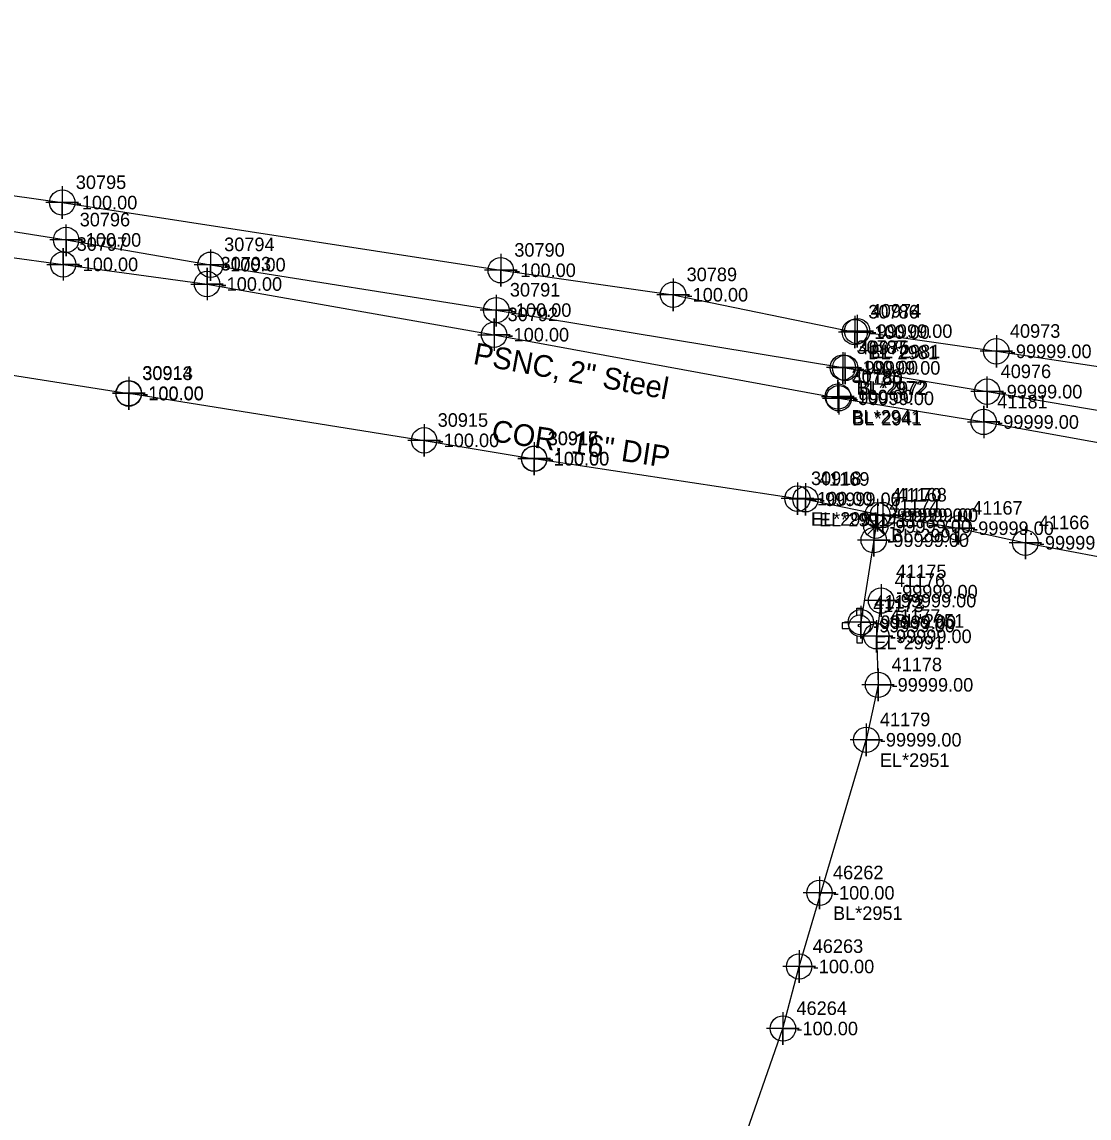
# Model space of a CAD drawing. Extents: x 2083698 to 2094313, y 743246 to 752873.
# Drawn here: x 2090310.6 to 2090507.3, y 744196.6 to 744398.7 of the extents above; entities that cross this region are included whole.
import ezdxf

# ---------------------------------------------------------------- set-up
doc = ezdxf.new("R2010")
doc.units = 0
for name, color, linetype in [('COGO Default Chain', 7, 'Continuous'), ('COGO Default Curve', 7, 'Continuous'), ('COGO Default Point Number', 7, 'Continuous'), ('Default Symbol CELL', 7, 'Continuous'), ('Default Symbol Cogo Number', 7, 'Continuous'), ('Exist Property Corner CELL', 7, 'Continuous'), ('Exist Property Iron Pin Leader', 7, 'Continuous'), ('Exist Property Iron Pin Text', 7, 'Continuous'), ('Exist Property Line', 7, 'Continuous'), ('Exist Property Line Leader', 7, 'Continuous'), ('Exist Property Monument Leader', 7, 'Continuous'), ('Exist Property Monument Text', 7, 'Continuous'), ('Exist Right of Way Easement Line', 7, 'Continuous'), ('Exist Right of Way Easement Line Leader', 7, 'Continuous'), ('Exist Right of Way Easement Line Text', 7, 'Continuous'), ('Exist Right of Way Line', 7, 'Continuous'), ('Exist Right of Way Line Leader', 7, 'Continuous'), ('Exist Right of Way Line Text', 7, 'Continuous'), ('Exist Right of Way Width CELL', 7, 'Continuous'), ('Exist Roads EOP', 7, 'Continuous'), ('Exist Roads EOP Leader', 7, 'Continuous'), ('Exist Roads EOP Text', 7, 'Continuous'), ('Exist Utilities Gas UG Line SUE LOS B', 7, 'Continuous'), ('Exist Utilities Gas UG Line SUE LOS B Text', 7, 'Continuous'), ('Exist Utilities Power Joint Use Telephone Cogo Elevation', 7, 'Continuous'), ('Exist Utilities Power Joint Use Telephone Cogo Number', 7, 'Continuous'), ('Exist Utilities Power UG Cable SUE LOS B', 7, 'Continuous'), ('Exist Utilities Telephone UG Conduit SUE LOS B', 7, 'Continuous'), ('Exist Utilities TV UG Cable SUE LOS B', 7, 'Continuous'), ('Exist Utilities Water UG Line SUE LOS B', 7, 'Continuous'), ('Exist Utilities Water UG Line SUE LOS B Text', 7, 'Continuous'), ('Old_Level_20', 7, 'Continuous'), ('Raster_Level_1', 7, 'Continuous'), ('Scratch_Level_2', 7, 'Continuous'), ('Scratch_Level_3', 7, 'Continuous')]:
    doc.layers.add(name, color=color, linetype=linetype)

msp = doc.modelspace()

# ---------------------------------------------------------------- linework, layer by layer
at = {"layer": 'COGO Default Curve'}
for points in [[(2090315.18, 744354.01), (2090321.18, 744354.01), (2090318.18, 744354.01), (2090318.18, 744357.01), (2090318.18, 744351.01)], [(2090341.72, 744350.39), (2090347.72, 744350.39), (2090344.72, 744350.39), (2090344.72, 744353.39), (2090344.72, 744347.39)], [(2090394.63, 744341.04), (2090400.63, 744341.04), (2090397.63, 744341.04), (2090397.63, 744344.04), (2090397.63, 744338.04)], [(2090458.03, 744329.64), (2090464.03, 744329.64), (2090461.03, 744329.64), (2090461.03, 744332.64), (2090461.03, 744326.64)], [(2090458.19, 744329.32), (2090464.19, 744329.32), (2090461.19, 744329.32), (2090461.19, 744332.32), (2090461.19, 744326.32)], [(2090484.91, 744324.95), (2090490.91, 744324.95), (2090487.91, 744324.95), (2090487.91, 744327.95), (2090487.91, 744321.95)]]:
    msp.add_lwpolyline(points, dxfattribs=at)
for centre in [(2090318.18, 744354.01), (2090344.72, 744350.39), (2090397.63, 744341.04), (2090461.03, 744329.64), (2090461.19, 744329.32), (2090487.91, 744324.95)]:
    msp.add_circle(centre, 2.34, dxfattribs=at)
at = {"layer": 'COGO Default Point Number'}
for points in [[(2090330.28, 744333.26), (2090330.28, 744327.26), (2090330.28, 744330.26), (2090333.28, 744330.26), (2090327.28, 744330.26)], [(2090330.28, 744333.18), (2090330.28, 744327.18), (2090330.28, 744330.18), (2090333.28, 744330.18), (2090327.28, 744330.18)], [(2090384.74, 744324.56), (2090384.74, 744318.56), (2090384.74, 744321.56), (2090387.74, 744321.56), (2090381.74, 744321.56)], [(2090405.02, 744321.15), (2090405.02, 744315.15), (2090405.02, 744318.15), (2090408.02, 744318.15), (2090402.02, 744318.15)], [(2090405.04, 744321.2), (2090405.04, 744315.2), (2090405.04, 744318.2), (2090408.04, 744318.2), (2090402.04, 744318.2)], [(2090453.57, 744313.81), (2090453.57, 744307.81), (2090453.57, 744310.81), (2090456.57, 744310.81), (2090450.57, 744310.81)], [(2090455.05, 744313.69), (2090455.05, 744307.69), (2090455.05, 744310.69), (2090458.05, 744310.69), (2090452.05, 744310.69)], [(2090468.33, 744310.75), (2090468.33, 744304.75), (2090468.33, 744307.75), (2090471.33, 744307.75), (2090465.33, 744307.75)], [(2090469.31, 744310.78), (2090469.31, 744304.78), (2090469.31, 744307.78), (2090472.31, 744307.78), (2090466.31, 744307.78)], [(2090483.29, 744308.36), (2090483.29, 744302.36), (2090483.29, 744305.36), (2090486.29, 744305.36), (2090480.29, 744305.36)], [(2090467.64, 744306.15), (2090467.64, 744300.15), (2090467.64, 744303.15), (2090470.64, 744303.15), (2090464.64, 744303.15)], [(2090495.59, 744305.68), (2090495.59, 744299.68), (2090495.59, 744302.68), (2090498.59, 744302.68), (2090492.59, 744302.68)], [(2090465.25, 744291.03), (2090465.25, 744285.03), (2090465.25, 744288.03), (2090468.25, 744288.03), (2090462.25, 744288.03)]]:
    msp.add_lwpolyline(points, dxfattribs=at)
for centre in [(2090330.28, 744330.26), (2090330.28, 744330.18), (2090384.74, 744321.56), (2090405.02, 744318.15), (2090405.04, 744318.2), (2090453.57, 744310.81), (2090455.05, 744310.69), (2090468.33, 744307.75), (2090469.31, 744307.78), (2090483.29, 744305.36), (2090467.64, 744303.15), (2090495.59, 744302.68), (2090465.25, 744288.03)]:
    msp.add_circle(centre, 2.34, dxfattribs=at)
at = {"layer": 'Exist Property Iron Pin Text'}
for points in [[(2090468.99, 744295.01), (2090468.99, 744289.01), (2090468.99, 744292.01), (2090471.99, 744292.01), (2090465.99, 744292.01)], [(2090468.13, 744288.43), (2090468.13, 744282.43), (2090468.13, 744285.43), (2090471.13, 744285.43), (2090465.13, 744285.43)], [(2090468.43, 744279.48), (2090468.43, 744273.48), (2090468.43, 744276.48), (2090471.43, 744276.48), (2090465.43, 744276.48)], [(2090466.27, 744269.34), (2090466.27, 744263.34), (2090466.27, 744266.34), (2090469.27, 744266.34), (2090463.27, 744266.34)], [(2090457.63, 744241.12), (2090457.63, 744235.12), (2090457.63, 744238.12), (2090460.63, 744238.12), (2090454.63, 744238.12)], [(2090453.89, 744227.54), (2090453.89, 744221.54), (2090453.89, 744224.54), (2090456.89, 744224.54), (2090450.89, 744224.54)], [(2090450.89, 744216.1), (2090450.89, 744210.1), (2090450.89, 744213.1), (2090453.89, 744213.1), (2090447.89, 744213.1)]]:
    msp.add_lwpolyline(points, dxfattribs=at)
for centre in [(2090468.99, 744292.01), (2090468.13, 744285.43), (2090468.43, 744276.48), (2090466.27, 744266.34), (2090457.63, 744238.12), (2090453.89, 744224.54), (2090450.89, 744213.1)]:
    msp.add_circle(centre, 2.34, dxfattribs=at)
at = {"layer": 'Exist Property Line Leader'}
for points in [[(2090318.02, 744368.41), (2090318.02, 744362.41), (2090318.02, 744365.41), (2090321.02, 744365.41), (2090315.02, 744365.41)], [(2090398.87, 744355.93), (2090398.87, 744349.93), (2090398.87, 744352.93), (2090401.87, 744352.93), (2090395.87, 744352.93)], [(2090430.64, 744351.41), (2090430.64, 744345.41), (2090430.64, 744348.41), (2090433.64, 744348.41), (2090427.64, 744348.41)], [(2090464.14, 744344.53), (2090464.14, 744338.53), (2090464.14, 744341.53), (2090467.14, 744341.53), (2090461.14, 744341.53)], [(2090464.58, 744344.7), (2090464.58, 744338.7), (2090464.58, 744341.7), (2090467.58, 744341.7), (2090461.58, 744341.7)], [(2090490.24, 744340.98), (2090490.24, 744334.98), (2090490.24, 744337.98), (2090493.24, 744337.98), (2090487.24, 744337.98)]]:
    msp.add_lwpolyline(points, dxfattribs=at)
for centre in [(2090318.02, 744365.41), (2090398.87, 744352.93), (2090430.64, 744348.41), (2090464.14, 744341.53), (2090464.58, 744341.7), (2090490.24, 744337.98)]:
    msp.add_circle(centre, 2.34, dxfattribs=at)
at = {"layer": 'Exist Right of Way Line Text'}
for points in [[(2090318.71, 744361.34), (2090318.74, 744355.52), (2090318.73, 744358.52), (2090321.74, 744358.52), (2090315.74, 744358.52)], [(2090345.34, 744356.77), (2090345.37, 744350.95), (2090345.35, 744353.95), (2090348.37, 744353.95), (2090342.37, 744353.95)], [(2090398.02, 744348.39), (2090398.05, 744342.58), (2090398.04, 744345.58), (2090401.05, 744345.58), (2090395.05, 744345.58)], [(2090461.92, 744337.81), (2090461.95, 744332), (2090461.94, 744335), (2090464.95, 744335), (2090458.95, 744335)], [(2090462.33, 744337.74), (2090462.36, 744331.92), (2090462.34, 744334.92), (2090465.36, 744334.92), (2090459.36, 744334.92)], [(2090488.51, 744333.35), (2090488.54, 744327.54), (2090488.53, 744330.54), (2090491.54, 744330.54), (2090485.54, 744330.54)]]:
    msp.add_lwpolyline(points, dxfattribs=at)
for centre in [(2090318.74, 744358.52), (2090345.37, 744353.95), (2090398.05, 744345.58), (2090461.95, 744335), (2090462.36, 744334.92), (2090488.54, 744330.54)]:
    msp.add_circle(centre, 2.34, dxfattribs=at)
at = {"layer": 'Exist Roads EOP'}
msp.add_lwpolyline([(2090469.6, 744307.29), (2090466.45, 744304.14), (2090468.02, 744305.72), (2090469.6, 744304.14), (2090466.45, 744307.29)], dxfattribs=at)
msp.add_circle((2090468.02, 744305.72), 2.23, dxfattribs=at)
at = {"layer": 'Exist Utilities Gas UG Line SUE LOS B'}
for points in [[(2089711.55, 744387.62), (2089756.53, 744385.83), (2089770.13, 744385.56), (2089791.66, 744384.63), (2089831.15, 744384.29), (2089852.65, 744384.93), (2089877.76, 744384.56), (2089910.17, 744383.48), (2089956.91, 744382.91), (2090010.13, 744381.65), (2090060.73, 744379.21), (2090117.92, 744377.86), (2090174.06, 744371.58), (2090201.47, 744368.61), (2090259.26, 744361.47), (2090264.98, 744360.29), (2090285.89, 744358.43), (2090318.18, 744354.01), (2090344.72, 744350.39), (2090397.63, 744341.04), (2090461.19, 744329.32)], [(2090461.19, 744329.32), (2090487.91, 744324.95), (2090517.18, 744319.69), (2090542.84, 744315.5), (2090566.72, 744310.47), (2090590.57, 744306.9), (2090618.26, 744302.32), (2090647, 744297.28), (2090679.19, 744292), (2090706.38, 744286.46), (2090732.53, 744282.44), (2090769.33, 744275.59), (2090790.43, 744272.14), (2090815.88, 744267.62), (2090833.41, 744265.34), (2090852.1, 744262.08), (2090862.55, 744260.39), (2090870.48, 744259.26), (2090891.68, 744256.92)]]:
    msp.add_lwpolyline(points, dxfattribs=at)
at = {"layer": 'Exist Utilities Power UG Cable SUE LOS B'}
for points in [[(2090468.99, 744292.01), (2090468.13, 744285.43), (2090468.43, 744276.48), (2090466.27, 744266.34)], [(2090377.35, 743925.53), (2090384.33, 743956.33), (2090390.69, 743987.52), (2090394.74, 743998.37), (2090397.24, 744005.48), (2090401.27, 744023.39), (2090406.08, 744051.45), (2090412.73, 744076.91), (2090420.03, 744103.97), (2090427.25, 744131.27), (2090433.9, 744157.45), (2090437.58, 744171.49), (2090442.95, 744190.35), (2090450.89, 744213.1), (2090453.89, 744224.54), (2090466.27, 744266.34)]]:
    msp.add_lwpolyline(points, dxfattribs=at)
at = {"layer": 'Exist Utilities Telephone UG Conduit SUE LOS B'}
for points in [[(2089543.2, 744398.02), (2089618.15, 744395.85), (2089665.91, 744394.38), (2089690.71, 744394.08), (2089710.79, 744393.02), (2089756.88, 744391.89), (2089831.79, 744390.27), (2089878.22, 744389.02), (2089910.45, 744388.28), (2089956.7, 744387.8), (2090010.24, 744385.92), (2090061.06, 744385.11), (2090118.44, 744382.35), (2090174.93, 744380.66), (2090202.11, 744377.17), (2090261.38, 744368.82), (2090283.03, 744364.22), (2090318.74, 744358.52), (2090345.37, 744353.95), (2090398.05, 744345.58), (2090461.95, 744335)], [(2090462.36, 744334.92), (2090488.54, 744330.54), (2090518.65, 744325.49)]]:
    msp.add_lwpolyline(points, dxfattribs=at)
at = {"layer": 'Exist Utilities TV UG Cable SUE LOS B'}
for points in [[(2089818.55, 744396.88), (2089855.21, 744398.72), (2089896.27, 744398.25), (2089929.74, 744398.05), (2089956.2, 744393.63), (2090010.98, 744390.83), (2090060.95, 744389.12), (2090118.27, 744387.79), (2090170.32, 744384.2), (2090201.62, 744382.33), (2090259.14, 744373.69), (2090318.02, 744365.41), (2090398.87, 744352.93), (2090430.64, 744348.41), (2090464.14, 744341.53)], [(2090464.58, 744341.7), (2090490.24, 744337.98), (2090519.65, 744333.6), (2090542.68, 744330.23), (2090567.11, 744325.5), (2090592.51, 744321.91), (2090619.05, 744316.63), (2090647.22, 744313.33), (2090660.52, 744312.34), (2090662.78, 744311.44), (2090662.54, 744309.61), (2090660.59, 744295.7), (2090657.83, 744275.6), (2090655.3, 744265.25), (2090654.22, 744261.01)]]:
    msp.add_lwpolyline(points, dxfattribs=at)
at = {"layer": 'Exist Utilities Water UG Line SUE LOS B'}
for points in [[(2090031.62, 744360.45), (2090061.58, 744359.55), (2090104.79, 744357.37), (2090104.78, 744357.38), (2090126.49, 744355.64), (2090157.05, 744353.17), (2090186.38, 744350.39), (2090228.99, 744344.98), (2090258.61, 744341.12), (2090292.45, 744336.17), (2090330.28, 744330.18), (2090330.28, 744330.26), (2090384.74, 744321.56), (2090405.02, 744318.15), (2090405.04, 744318.2), (2090453.57, 744310.81)], [(2090455.05, 744310.69), (2090469.31, 744307.78), (2090483.29, 744305.36), (2090495.59, 744302.68), (2090517.19, 744298.58), (2090540.95, 744294.42), (2090568, 744290.02), (2090579.85, 744288), (2090599.72, 744285.07), (2090608.58, 744283.42), (2090615.61, 744281.71)], [(2090468.33, 744307.75), (2090467.64, 744303.15), (2090465.25, 744288.03)]]:
    msp.add_lwpolyline(points, dxfattribs=at)
at = {"layer": 'Raster_Level_1'}
msp.add_line((2090465.03, 744287.4), (2090465.03, 744287.4), dxfattribs=at)
for points in [[(2090464.52, 744289.31), (2090464.52, 744290.6), (2090465.54, 744290.6), (2090465.54, 744289.29)], [(2090463.12, 744287.91), (2090461.83, 744287.91), (2090461.83, 744286.89), (2090463.12, 744286.89)], [(2090464.52, 744285.49), (2090464.52, 744284.2), (2090465.54, 744284.2), (2090465.54, 744285.51)]]:
    msp.add_lwpolyline(points, dxfattribs=at)
for radius in [1.98, 0.243]:
    msp.add_circle((2090465.03, 744287.4), radius, dxfattribs=at)

# ---------------------------------------------------------------- texts
at = {"layer": 'COGO Default Chain'}
for s, p in [('-100.00', (2090320.68, 744352.76)), ('-100.00', (2090347.22, 744349.14)), ('-100.00', (2090400.13, 744339.79)), ('-100.00', (2090463.53, 744328.39)), ('-99999.00', (2090463.69, 744328.07)), ('-99999.00', (2090490.41, 744323.7))]:
    msp.add_text(s, height=2.5, dxfattribs=at).set_placement(p)
at = {"layer": 'Default Symbol CELL'}
for s, p in [('30795', (2090320.52, 744367.91)), ('30790', (2090401.37, 744355.43)), ('30789', (2090433.14, 744350.91)), ('30786', (2090466.64, 744344.03)), ('40974', (2090467.08, 744344.2)), ('40973', (2090492.74, 744340.48))]:
    msp.add_text(s, height=2.5, dxfattribs=at).set_placement(p)
at = {"layer": 'Default Symbol Cogo Number'}
for s, p in [('-100.00', (2090320.52, 744364.16)), ('-100.00', (2090401.37, 744351.68)), ('-100.00', (2090433.14, 744347.16)), ('-100.00', (2090466.64, 744340.28)), ('-99999.00', (2090467.08, 744340.45)), ('-99999.00', (2090492.74, 744336.73))]:
    msp.add_text(s, height=2.5, dxfattribs=at).set_placement(p)
at = {"layer": 'Exist Property Corner CELL'}
for s, p in [('BL*2981', (2090466.64, 744336.53)), ('EL*2981', (2090467.08, 744336.7))]:
    msp.add_text(s, height=2.5, dxfattribs=at).set_placement(p)
at = {"layer": 'Exist Property Iron Pin Leader'}
for s, p in [('41176', (2090471.49, 744294.51)), ('41177', (2090470.63, 744287.93)), ('41178', (2090470.93, 744278.98)), ('41179', (2090468.77, 744268.84)), ('46262', (2090460.13, 744240.62)), ('46263', (2090456.39, 744227.04)), ('46264', (2090453.39, 744215.6))]:
    msp.add_text(s, height=2.5, dxfattribs=at).set_placement(p)
at = {"layer": 'Exist Property Line'}
for s, p in [('-100.00', (2090332.78, 744329.01)), ('-100.00', (2090332.78, 744328.93)), ('-100.00', (2090387.24, 744320.31)), ('-100.00', (2090407.52, 744316.9)), ('-100.00', (2090407.54, 744316.95)), ('-100.00', (2090456.07, 744309.56)), ('-99999.00', (2090457.55, 744309.44)), ('-99999.00', (2090470.83, 744306.5)), ('-99999.00', (2090471.81, 744306.53)), ('-99999.00', (2090485.79, 744304.11)), ('-99999.00', (2090470.14, 744301.9)), ('-99999.00', (2090498.09, 744301.43)), ('-99999.00', (2090467.75, 744286.78))]:
    msp.add_text(s, height=2.5, dxfattribs=at).set_placement(p)
at = {"layer": 'Exist Property Monument Leader'}
for s, p in [('BL*2951', (2090471.49, 744287.01)), ('EL*2951', (2090468.77, 744261.34)), ('BL*2951', (2090460.13, 744233.12))]:
    msp.add_text(s, height=2.5, dxfattribs=at).set_placement(p)
at = {"layer": 'Exist Property Monument Text'}
for s, p in [('-99999.00', (2090471.49, 744290.76)), ('-99999.00', (2090470.63, 744284.18)), ('-99999.00', (2090470.93, 744275.23)), ('-99999.00', (2090468.77, 744265.09)), ('-100.00', (2090460.13, 744236.87)), ('-100.00', (2090456.39, 744223.29)), ('-100.00', (2090453.39, 744211.85))]:
    msp.add_text(s, height=2.5, dxfattribs=at).set_placement(p)
at = {"layer": 'Exist Right of Way Easement Line'}
for p in [(2090463.53, 744324.64), (2090463.69, 744324.32)]:
    msp.add_text('BL*2941', height=2.5, dxfattribs=at).set_placement(p)
at = {"layer": 'Exist Right of Way Easement Line Leader'}
msp.add_text('-99999.00', height=2.5, dxfattribs=at).set_placement((2090467.53, 744286.15))
at = {"layer": 'Exist Right of Way Easement Line Text'}
msp.add_text('41173', height=2.5, dxfattribs=at).set_placement((2090467.53, 744289.9))
at = {"layer": 'Exist Right of Way Line'}
for s, p in [('30914', (2090332.78, 744332.76)), ('30913', (2090332.78, 744332.68)), ('30915', (2090387.24, 744324.06)), ('30916', (2090407.52, 744320.65)), ('30917', (2090407.54, 744320.7)), ('30918', (2090456.07, 744313.31)), ('41169', (2090457.55, 744313.19)), ('41170', (2090470.83, 744310.25)), ('41168', (2090471.81, 744310.28)), ('41167', (2090485.79, 744307.86)), ('41171', (2090470.14, 744305.65)), ('41166', (2090498.09, 744305.18)), ('41172', (2090467.75, 744290.53))]:
    msp.add_text(s, height=2.5, dxfattribs=at).set_placement(p)
at = {"layer": 'Exist Right of Way Line Leader'}
for s, p in [('30796', (2090321.24, 744361.02)), ('30794', (2090347.87, 744356.45)), ('30791', (2090400.55, 744348.08)), ('30787', (2090464.45, 744337.5)), ('40975', (2090464.86, 744337.42)), ('40976', (2090491.04, 744333.04))]:
    msp.add_text(s, height=2.5, dxfattribs=at).set_placement(p)
at = {"layer": 'Exist Right of Way Width CELL'}
for s, p in [('EL*2991', (2090456.07, 744305.81)), ('EL*2991', (2090457.55, 744305.69)), ('BL*2991', (2090470.83, 744302.75)), ('EL*2991', (2090467.75, 744283.03))]:
    msp.add_text(s, height=2.5, dxfattribs=at).set_placement(p)
at = {"layer": 'Exist Roads EOP Leader'}
msp.add_text('-99999.00', height=2.5, dxfattribs=at).set_placement((2090470.52, 744304.47))
at = {"layer": 'Exist Roads EOP Text'}
msp.add_text('41174', height=2.5, dxfattribs=at).set_placement((2090470.52, 744308.22))
at = {"layer": 'Exist Utilities Gas UG Line SUE LOS B Text'}
msp.add_text('PSNC, 2" Steel', height=4, rotation=349.5452, dxfattribs=at).set_placement((2090393.61, 744335.68))
at = {"layer": 'Exist Utilities Power Joint Use Telephone Cogo Elevation'}
msp.add_text('-99999.00', height=2.5, dxfattribs=at).set_placement((2090471.75, 744292.4))
at = {"layer": 'Exist Utilities Power Joint Use Telephone Cogo Number'}
msp.add_text('41175', height=2.5, dxfattribs=at).set_placement((2090471.75, 744296.15))
at = {"layer": 'Exist Utilities Water UG Line SUE LOS B Text'}
msp.add_text('COR, 16" DIP', height=4, rotation=351.3449, dxfattribs=at).set_placement((2090396.99, 744321.44))
at = {"layer": 'Old_Level_20'}
for s, p in [('30797', (2090320.68, 744356.51)), ('30793', (2090347.22, 744352.89)), ('30792', (2090400.13, 744343.54)), ('30788', (2090463.53, 744332.14)), ('41180', (2090463.69, 744331.82)), ('41181', (2090490.41, 744327.45))]:
    msp.add_text(s, height=2.5, dxfattribs=at).set_placement(p)
at = {"layer": 'Scratch_Level_2'}
for s, p in [('-100.00', (2090321.24, 744357.27)), ('-100.00', (2090347.87, 744352.7)), ('-100.00', (2090400.55, 744344.33)), ('-100.00', (2090464.45, 744333.75)), ('-99999.00', (2090464.86, 744333.67)), ('-99999.00', (2090491.04, 744329.29))]:
    msp.add_text(s, height=2.5, dxfattribs=at).set_placement(p)
at = {"layer": 'Scratch_Level_3'}
for p in [(2090464.45, 744330), (2090464.86, 744329.92)]:
    msp.add_text('BL*2972', height=2.5, dxfattribs=at).set_placement(p)

doc.saveas('drawing.dxf')
